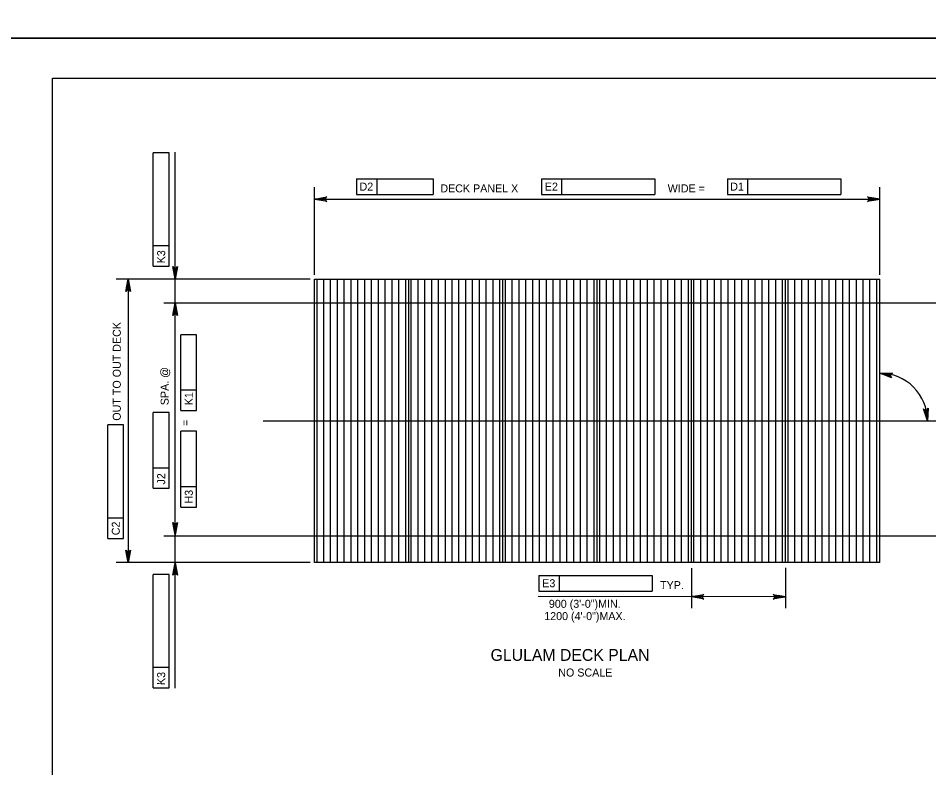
# Model space of a CAD drawing. Extents: x 638175 to 640495, y 294277 to 298435.
# Drawn here: x 639303.6 to 639645, y 295785.9 to 296067 of the extents above; entities that cross this region are included whole.
import ezdxf

# ---------------------------------------------------------------- set-up
doc = ezdxf.new("R2010")
doc.units = 0
for name, color, linetype in [('2', 7, 'Continuous'), ('4', 7, 'Continuous'), ('5', 7, 'Continuous'), ('PLT-BNDY', 7, 'Continuous')]:
    doc.layers.add(name, color=color, linetype=linetype)

msp = doc.modelspace()

# ---------------------------------------------------------------- linework, layer by layer
at = {"layer": '2'}
for p, q in [((639316.46, 295480.46), (639316.46, 296044.46)), ((639316.46, 296044.46), (640102.46, 296044.46)), ((639414.65, 295969.18), (639626.62, 295969.18)), ((639414.65, 295862.88), (639414.65, 295969.18)), ((639449.98, 295862.88), (639449.98, 295969.18)), ((639485.3, 295862.88), (639485.3, 295969.18)), ((639520.63, 295862.88), (639520.63, 295969.18)), ((639555.96, 295862.88), (639555.96, 295969.18)), ((639591.29, 295862.88), (639591.29, 295969.18)), ((639626.62, 295862.88), (639626.62, 295969.18)), ((639626.62, 295862.88), (639414.65, 295862.88))]:
    msp.add_line(p, q, dxfattribs=at)
at = {"layer": '4'}
for p, q in [((639354.22, 295974.01), (639354.22, 296016.53)), ((639360.12, 296016.53), (639354.22, 296016.53)), ((639360.12, 295974.01), (639360.12, 296016.53)), ((639362.43, 295815.8), (639362.43, 296016.77)), ((639430.45, 296006.78), (639459.11, 296006.78)), ((639430.45, 296006.78), (639430.45, 296000.87)), ((639438.01, 296006.78), (639438.01, 296000.87)), ((639459.11, 296006.78), (639459.11, 296000.87)), ((639499.72, 296006.78), (639542.24, 296006.78)), ((639499.72, 296006.78), (639499.72, 296000.87)), ((639507.28, 296006.78), (639507.28, 296000.87)), ((639542.24, 296006.78), (639542.24, 296000.87)), ((639569.5, 296006.78), (639612.02, 296006.78)), ((639569.5, 296006.78), (639569.5, 296000.87)), ((639577.06, 296006.78), (639577.06, 296000.87)), ((639612.02, 296006.78), (639612.02, 296000.87)), ((639414.65, 295970.74), (639414.65, 296003.66)), ((639626.62, 295970.74), (639626.62, 296003.66)), ((639430.45, 296000.87), (639459.11, 296000.87)), ((639499.72, 296000.87), (639542.24, 296000.87)), ((639569.5, 296000.87), (639612.02, 296000.87)), ((639414.65, 295999.16), (639626.62, 295999.16)), ((639360.12, 295981.57), (639354.22, 295981.57)), ((639354.22, 295974.01), (639360.12, 295974.01)), ((639413.08, 295969.18), (639340.34, 295969.18)), ((639344.84, 295969.18), (639344.84, 295862.88)), ((639358.14, 295960.21), (639648.51, 295960.21)), ((639364.58, 295919.91), (639364.58, 295948.31)), ((639370.48, 295948.31), (639364.58, 295948.31)), ((639370.48, 295919.9), (639370.48, 295948.31)), ((639370.48, 295927.46), (639364.58, 295927.47)), ((639354.22, 295890.73), (639354.22, 295919.14)), ((639360.12, 295919.13), (639354.22, 295919.14)), ((639360.12, 295890.73), (639360.12, 295919.13)), ((639364.58, 295919.91), (639370.48, 295919.9)), ((639337.2, 295871.94), (639337.2, 295914.46)), ((639343.11, 295914.46), (639337.2, 295914.46)), ((639343.11, 295871.93), (639343.11, 295914.46)), ((639395.36, 295916.03), (639648.51, 295916.03)), ((639364.58, 295883.68), (639364.58, 295912.08)), ((639370.48, 295912.08), (639364.58, 295912.08)), ((639370.48, 295883.67), (639370.48, 295912.08)), ((639360.12, 295898.29), (639354.22, 295898.3)), ((639354.22, 295890.73), (639360.12, 295890.73)), ((639370.48, 295891.23), (639364.58, 295891.24)), ((639364.58, 295883.68), (639370.48, 295883.67)), ((639343.11, 295879.5), (639337.2, 295879.5)), ((639337.2, 295871.94), (639343.11, 295871.93)), ((639358.14, 295872.94), (639648.51, 295872.94)), ((639413.08, 295862.88), (639340.34, 295862.88)), ((639555.96, 295860.81), (639555.96, 295845.83)), ((639591.29, 295860.88), (639591.28, 295845.83)), ((639354.22, 295815.93), (639354.22, 295858.45)), ((639360.12, 295858.44), (639354.22, 295858.45)), ((639360.12, 295815.92), (639360.12, 295858.44)), ((639498.77, 295858.07), (639541.29, 295858.07)), ((639498.77, 295858.07), (639498.77, 295852.17)), ((639506.33, 295858.07), (639506.33, 295852.17)), ((639541.29, 295858.07), (639541.29, 295852.17)), ((639591.28, 295850.08), (639498.58, 295850.1)), ((639498.77, 295852.17), (639541.29, 295852.17)), ((639360.12, 295823.48), (639354.22, 295823.49)), ((639354.22, 295815.93), (639360.12, 295815.92))]:
    msp.add_line(p, q, dxfattribs=at)
for points in [[(639414.65, 295999.16), (639419.31, 296000.03), (639418.95, 295999.78), (639418.76, 295999.47), (639418.71, 295999.16), (639418.76, 295998.84), (639418.95, 295998.53), (639419.31, 295998.28), (639414.65, 295999.16), (639418.95, 295998.53), (639418.76, 295998.84), (639414.65, 295999.16), (639418.71, 295999.16), (639418.76, 295999.47), (639414.65, 295999.16), (639418.95, 295999.78)], [(639626.62, 295999.16), (639621.96, 295998.28), (639622.31, 295998.53), (639622.5, 295998.84), (639622.55, 295999.16), (639622.5, 295999.47), (639622.31, 295999.78), (639621.96, 296000.03), (639626.62, 295999.16), (639622.31, 295999.78), (639622.5, 295999.47), (639626.62, 295999.16), (639622.55, 295999.16), (639622.5, 295998.84), (639626.62, 295999.16), (639622.31, 295998.53)], [(639362.43, 295969.18), (639361.55, 295973.84), (639361.8, 295973.48), (639362.11, 295973.29), (639362.43, 295973.24), (639362.74, 295973.29), (639363.05, 295973.48), (639363.3, 295973.84), (639362.43, 295969.18), (639363.05, 295973.48), (639362.74, 295973.29), (639362.43, 295969.18), (639362.43, 295973.24), (639362.11, 295973.29), (639362.43, 295969.18), (639361.8, 295973.48)], [(639344.84, 295969.18), (639345.71, 295964.52), (639345.47, 295964.87), (639345.15, 295965.06), (639344.84, 295965.11), (639344.53, 295965.06), (639344.22, 295964.87), (639343.97, 295964.52), (639344.84, 295969.18), (639344.22, 295964.87), (639344.53, 295965.06), (639344.84, 295969.18), (639344.84, 295965.11), (639345.15, 295965.06), (639344.84, 295969.18), (639345.47, 295964.87)], [(639362.43, 295960.21), (639363.3, 295955.55), (639363.05, 295955.91), (639362.74, 295956.09), (639362.43, 295956.15), (639362.11, 295956.09), (639361.8, 295955.91), (639361.55, 295955.55), (639362.43, 295960.21), (639361.8, 295955.91), (639362.11, 295956.09), (639362.43, 295960.21), (639362.43, 295956.15), (639362.74, 295956.09), (639362.43, 295960.21), (639363.05, 295955.91)], [(639626.62, 295933.93), (639631.36, 295933.89), (639630.96, 295933.71), (639630.72, 295933.44), (639630.61, 295933.15), (639630.6, 295932.83), (639630.72, 295932.49), (639631.02, 295932.17), (639626.62, 295933.93), (639630.72, 295932.49), (639630.6, 295932.83), (639626.62, 295933.93), (639630.61, 295933.15), (639630.72, 295933.44), (639626.62, 295933.93), (639630.96, 295933.71)], [(639644.47, 295916.03), (639643.01, 295920.54), (639643.3, 295920.22), (639643.63, 295920.07), (639643.95, 295920.06), (639644.26, 295920.15), (639644.54, 295920.37), (639644.74, 295920.76), (639644.47, 295916.03), (639644.54, 295920.37), (639644.26, 295920.15), (639644.47, 295916.03), (639643.95, 295920.06), (639643.63, 295920.07), (639644.47, 295916.03), (639643.3, 295920.22)], [(639362.38, 295873.23), (639361.5, 295877.89), (639361.75, 295877.53), (639362.07, 295877.34), (639362.38, 295877.29), (639362.69, 295877.34), (639363, 295877.53), (639363.25, 295877.89), (639362.38, 295873.23), (639363, 295877.53), (639362.69, 295877.34), (639362.38, 295873.23), (639362.38, 295877.29), (639362.07, 295877.34), (639362.38, 295873.23), (639361.75, 295877.53)], [(639344.84, 295862.88), (639343.97, 295867.54), (639344.22, 295867.18), (639344.53, 295867), (639344.84, 295866.94), (639345.15, 295867), (639345.47, 295867.18), (639345.71, 295867.54), (639344.84, 295862.88), (639345.47, 295867.18), (639345.15, 295867), (639344.84, 295862.88), (639344.84, 295866.94), (639344.53, 295867), (639344.84, 295862.88), (639344.22, 295867.18)], [(639362.4, 295862.75), (639363.28, 295858.09), (639363.03, 295858.45), (639362.72, 295858.63), (639362.4, 295858.68), (639362.09, 295858.63), (639361.78, 295858.45), (639361.53, 295858.09), (639362.4, 295862.75), (639361.78, 295858.45), (639362.09, 295858.63), (639362.4, 295862.75), (639362.4, 295858.68), (639362.72, 295858.63), (639362.4, 295862.75), (639363.03, 295858.45)], [(639555.96, 295850.09), (639560.62, 295850.96), (639560.26, 295850.71), (639560.07, 295850.4), (639560.02, 295850.09), (639560.07, 295849.77), (639560.26, 295849.46), (639560.62, 295849.21), (639555.96, 295850.09), (639560.26, 295849.46), (639560.07, 295849.77), (639555.96, 295850.09), (639560.02, 295850.09), (639560.07, 295850.4), (639555.96, 295850.09), (639560.26, 295850.71)], [(639591.28, 295850.08), (639586.62, 295849.21), (639586.98, 295849.45), (639587.17, 295849.77), (639587.22, 295850.08), (639587.17, 295850.39), (639586.98, 295850.7), (639586.62, 295850.95), (639591.28, 295850.08), (639586.98, 295850.7), (639587.17, 295850.39), (639591.28, 295850.08), (639587.22, 295850.08), (639587.17, 295849.77), (639591.28, 295850.08), (639586.98, 295849.45)]]:
    msp.add_lwpolyline(points, dxfattribs=at)
for points in [[(639417.65, 295999.66), (639417.65, 295998.66), (639414.65, 295999.16)], [(639623.62, 295999.66), (639623.62, 295998.66), (639626.62, 295999.16)], [(639362.92, 295972.13), (639361.93, 295972.13), (639362.43, 295969.18)], [(639344.34, 295966.18), (639345.34, 295966.18), (639344.84, 295969.18)], [(639362.92, 295957.26), (639361.93, 295957.26), (639362.43, 295960.21)], [(639362.92, 295875.89), (639361.93, 295875.89), (639362.43, 295872.94)], [(639344.34, 295865.88), (639345.34, 295865.88), (639344.84, 295862.88)], [(639362.92, 295859.93), (639361.93, 295859.93), (639362.43, 295862.88)], [(639558.79, 295850.56), (639558.79, 295849.61), (639555.96, 295850.09)], [(639588.45, 295850.55), (639588.45, 295849.61), (639591.28, 295850.08)]]:
    msp.add_lwpolyline(points, close=True, dxfattribs=at)
msp.add_arc((639626.62, 295916.03), 17.85, 0.0023, 90.0027, dxfattribs=at)
at = {"layer": '5'}
for p, q in [((639415.6, 295862.88), (639415.6, 295969.18)), ((639418.16, 295862.88), (639418.16, 295969.18)), ((639420.72, 295862.88), (639420.72, 295969.18)), ((639423.28, 295862.88), (639423.28, 295969.18)), ((639425.83, 295862.88), (639425.83, 295969.18)), ((639428.39, 295862.88), (639428.39, 295969.18)), ((639430.95, 295862.88), (639430.95, 295969.18)), ((639433.5, 295862.88), (639433.5, 295969.18)), ((639436.06, 295862.88), (639436.06, 295969.18)), ((639438.62, 295862.88), (639438.62, 295969.18)), ((639441.18, 295862.88), (639441.18, 295969.18)), ((639443.73, 295862.88), (639443.73, 295969.18)), ((639446.29, 295862.88), (639446.29, 295969.18)), ((639448.85, 295862.88), (639448.85, 295969.18)), ((639450.93, 295862.88), (639450.93, 295969.18)), ((639453.49, 295862.88), (639453.49, 295969.18)), ((639456.05, 295862.88), (639456.05, 295969.18)), ((639458.6, 295862.88), (639458.6, 295969.18)), ((639461.16, 295862.88), (639461.16, 295969.18)), ((639463.72, 295862.88), (639463.72, 295969.18)), ((639466.28, 295862.88), (639466.28, 295969.18)), ((639468.83, 295862.88), (639468.83, 295969.18)), ((639471.39, 295862.88), (639471.39, 295969.18)), ((639473.95, 295862.88), (639473.95, 295969.18)), ((639476.51, 295862.88), (639476.51, 295969.18)), ((639479.06, 295862.88), (639479.06, 295969.18)), ((639481.62, 295862.88), (639481.62, 295969.18)), ((639484.18, 295862.88), (639484.18, 295969.18)), ((639486.26, 295862.88), (639486.26, 295969.18)), ((639488.82, 295862.88), (639488.82, 295969.18)), ((639491.38, 295862.88), (639491.38, 295969.18)), ((639493.93, 295862.88), (639493.93, 295969.18)), ((639496.49, 295862.88), (639496.49, 295969.18)), ((639499.05, 295862.88), (639499.05, 295969.18)), ((639501.61, 295862.88), (639501.61, 295969.18)), ((639504.16, 295862.88), (639504.16, 295969.18)), ((639506.72, 295862.88), (639506.72, 295969.18)), ((639509.28, 295862.88), (639509.28, 295969.18)), ((639511.83, 295862.88), (639511.83, 295969.18)), ((639514.39, 295862.88), (639514.39, 295969.18)), ((639516.95, 295862.88), (639516.95, 295969.18)), ((639519.51, 295862.88), (639519.51, 295969.18)), ((639521.59, 295862.88), (639521.59, 295969.18)), ((639524.15, 295862.88), (639524.15, 295969.18)), ((639526.7, 295862.88), (639526.7, 295969.18)), ((639529.26, 295862.88), (639529.26, 295969.18)), ((639531.82, 295862.88), (639531.82, 295969.18)), ((639534.38, 295862.88), (639534.38, 295969.18)), ((639536.93, 295862.88), (639536.93, 295969.18)), ((639539.49, 295862.88), (639539.49, 295969.18)), ((639542.05, 295862.88), (639542.05, 295969.18)), ((639544.61, 295862.88), (639544.61, 295969.18)), ((639547.16, 295862.88), (639547.16, 295969.18)), ((639549.72, 295862.88), (639549.72, 295969.18)), ((639552.28, 295862.88), (639552.28, 295969.18)), ((639554.83, 295862.88), (639554.83, 295969.18)), ((639556.92, 295862.88), (639556.92, 295969.18)), ((639559.48, 295862.88), (639559.48, 295969.18)), ((639562.03, 295862.88), (639562.03, 295969.18)), ((639564.59, 295862.88), (639564.59, 295969.18)), ((639567.15, 295862.88), (639567.15, 295969.18)), ((639569.7, 295862.88), (639569.7, 295969.18)), ((639572.26, 295862.88), (639572.26, 295969.18)), ((639574.82, 295862.88), (639574.82, 295969.18)), ((639577.38, 295862.88), (639577.38, 295969.18)), ((639579.93, 295862.88), (639579.93, 295969.18)), ((639582.49, 295862.88), (639582.49, 295969.18)), ((639585.05, 295862.88), (639585.05, 295969.18)), ((639587.6, 295862.88), (639587.6, 295969.18)), ((639590.16, 295862.88), (639590.16, 295969.18)), ((639592.25, 295862.88), (639592.25, 295969.18)), ((639594.8, 295862.88), (639594.8, 295969.18)), ((639597.36, 295862.88), (639597.36, 295969.18)), ((639599.92, 295862.88), (639599.92, 295969.18)), ((639602.47, 295862.88), (639602.47, 295969.18)), ((639605.03, 295862.88), (639605.03, 295969.18)), ((639607.59, 295862.88), (639607.59, 295969.18)), ((639610.15, 295862.88), (639610.15, 295969.18)), ((639612.7, 295862.88), (639612.7, 295969.18)), ((639615.26, 295862.88), (639615.26, 295969.18)), ((639617.82, 295862.88), (639617.82, 295969.18)), ((639620.37, 295862.88), (639620.37, 295969.18)), ((639622.93, 295862.88), (639622.93, 295969.18)), ((639625.49, 295862.88), (639625.49, 295969.18))]:
    msp.add_line(p, q, dxfattribs=at)
at = {"layer": 'PLT-BNDY'}
for points in [[(639276.46, 296653.46), (640117.46, 296653.46), (640117.46, 296059.46), (639276.46, 296059.46)], [(639276.46, 296059.46), (640117.46, 296059.46), (640117.46, 295465.46), (639276.46, 295465.46)]]:
    msp.add_lwpolyline(points, close=True, dxfattribs=at)

# ---------------------------------------------------------------- texts
at = {"layer": '4'}
for s, rotation, p in [('D2', 359.9382, (639431.53, 296002.33)), ('E2', 359.9382, (639501.01, 296002.33)), ('D1', 359.9382, (639570.53, 296002.33)), ('K3', 89.9382, (639358.67, 295975.04)), ('OUT TO OUT DECK', 90, (639342.03, 295916.06)), ('SPA. @', 90, (639359.97, 295921.87)), ('K1', 89.9382, (639369.03, 295921.83)), ('=', 90, (639367.7, 295914.11)), ('J2', 89.9382, (639358.67, 295892.13)), ('H3', 89.9382, (639369.03, 295884.99)), ('C2', 89.9382, (639341.65, 295873.12)), ('E3', 359.9382, (639500.05, 295853.62)), ('TYP.', 359.9382, (639544.22, 295852.92)), ('K3', 89.9382, (639358.67, 295816.95))]:
    msp.add_text(s, height=3, rotation=rotation, dxfattribs=at).set_placement(p)
for s, height, p in [('DECK PANEL X', 3, (639461.84, 296001.66)), ('WIDE =', 3, (639547.09, 296001.66)), ('900 (3\'-0")MIN.', 3, (639502.53, 295845.91)), ('1200 (4\'-0")MAX.', 3, (639500.79, 295841.3)), ('GLULAM DECK PLAN', 4.4292, (639480.68, 295826.02)), ('NO SCALE', 3, (639506.06, 295820.14))]:
    msp.add_text(s, height=height, dxfattribs=at).set_placement(p)

doc.saveas('drawing.dxf')
